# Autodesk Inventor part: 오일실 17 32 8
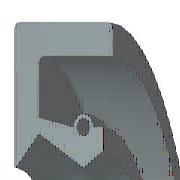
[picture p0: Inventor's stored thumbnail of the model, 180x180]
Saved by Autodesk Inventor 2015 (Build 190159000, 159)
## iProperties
IsCustomPart: 1
Created: 2012-02
Part Number: 오일실 17 32 8
Material: 고무
Description: 오일-실
Document SubType Name: Modeling
Standard: KS B 2804
Designer: mduedu
Standards Organization: KS
Language: ko-KR
Size Designation: D - 17 32 8
Categories: <MemberInstance><Categories><Category DisplayName="샤프트 부품" InternalName="7f7aeb1f-a693-4053-b835-cee3144e0d98" Mnemonic="SHFT"><Category DisplayName="실링" Intern
Density: 0.93 g/cm^3
Appearance: Rubber - Black - Version 1.1
Mass: 2.28027 g
Surface Area: 32.1224 cm^2
Volume: 2.45191 cm^3
Author: mduedu
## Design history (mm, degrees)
revolve "본체" stored, may be unused: angle "d17" = 90 deg
revolve "스프링1" stored, may be unused: angle "d18" = 90 deg
body "Solid1"
sketch "스케치1"
  geometry: L1 (0, 16)-(8, 16); L2 (8, 14.25)-(1.75, 14.25); L3 (1.75, 10.25)-(4.9, 8.5); L4 (4.9, 8.5)-(0, 8.5); L5 (0, 0)-(9.586, 0) reference; L6 (4.9, 8.5)-(6.3, 9.375); L7 (0, 18)-(0, -3) reference; L8 (-1.941, 0)-(11.507, 0) reference; L9 (4.2, 10.6)-(1.75, 11.21); L10 (1.75, 11.21)-(1.75, 14.25); L11 (0, 16)-(0, 8.588); L12 (4.9, 8.5)-(0, 8.5); L13 (1.75, 10.25)-(0.152, 8.528); L14 (8, 16)-(8, 14.25); L15 (5.6, 10.6)-(6.3, 10.6); L16 (6.3, 10.6)-(6.3, 9.375); C1 r 0.455 at (4.9, 10.6); A1 r 0.7 centre (4.9, 10.6) between (5.6, 10.6) and (4.2, 10.6); A2 r 0.088 centre (0.088, 8.588) between (0, 8.588) and (0.152, 8.528); 1 further point
  constraints: 28 end point, 5 horizontal alignment, 5 point on line, 4 point on circle, 4 vertical alignment, 3 centre point, 3 tangent, 2 collinear, 2 horizontal, 2 perpendicular, 1 coincident, 1 parallel
  dimensions: "d0" = 32 diameter of L1 L5 (= SD2); "d1" = 1.75 distance of L1.end L2.start (= SD); "d2" = 0.91 diameter of C1 (= SPDI); "d3" = 1.4 diameter of A1 (= SPDA); "d4" = 17 diameter of L3.end L5 (= NND); "d5" = 20.5 diameter of L3.start L5 (= TKDM); "d7" = 22.42 diameter of L9.end L5 (= TKDM + 0.24 x SWDT); "d8" = 1.75 distance between parallel lines of L11 L10 (= SD); "d9" = 4.9 distance from line of L11 C1.centre (= SPDST); "d10" = 21.2 diameter of C1.centre L5 (= HLDM); "d11" = 0.0875 radius of A2 (= 0.25 x LAB); "d12" = 6.3 distance between parallel lines of L11 L16 (= SDI); "d13" = 18.75 diameter of L6.end L5 (= ABDM); "d14" = 8 distance from line of L11 L1.end (= SWDT)
fillet "모깎기1" dims "d6" = 0.3 (= RR)
other parameters: "SD2" = 32 [user parameter; used in 1 equation term], "SWDT" = 8 [user parameter; used in 2 equation terms], "RR" = 0.3 [user parameter; used in 1 equation term], "SD" = 1.75 [user parameter; used in 2 equation terms], "NND" = 17 [user parameter; used in 1 equation term], "SPDA" = 1.4 [user parameter; used in 1 equation term], "SPDI" = 0.91 [user parameter; used in 1 equation term], "TKDM" = 20.5 [user parameter; used in 2 equation terms], "HLDM" = 21.2 [user parameter; used in 1 equation term], "ABDM" = 18.75 [user parameter; used in 1 equation term], "SDI" = 6.3 [user parameter; used in 1 equation term], "SPDST" = 4.9 [user parameter; used in 1 equation term], "LAB" = 0.35 [user parameter; used in 1 equation term], "d15" = 0, "d16" = 0, "d19" = 0
